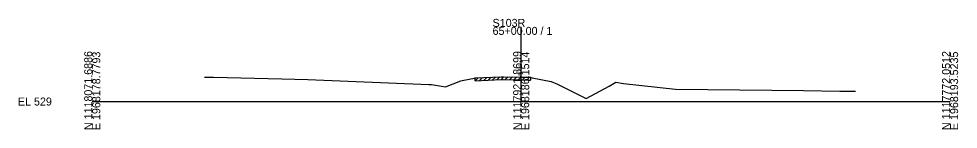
# Model space of a CAD drawing. Extents: x 974 to 1303, y 990 to 10019.
# Drawn here: x 974.3 to 1302.8, y 7490.3 to 7529 of the extents above; entities that cross this region are included whole.
import ezdxf

# ---------------------------------------------------------------- set-up
doc = ezdxf.new("R2010")
doc.units = 0
for name, color, linetype in [('Level 10', 7, 'Continuous'), ('Level 60', 7, 'Continuous'), ('Level 61', 7, 'Continuous'), ('Level 63', 7, 'Continuous')]:
    doc.layers.add(name, color=color, linetype=linetype)

msp = doc.modelspace()

# ---------------------------------------------------------------- linework, layer by layer
at = {"layer": 'Level 60'}
for p, q in [((1039.27, 7508.49), (1042.35, 7508.48)), ((1042.35, 7508.48), (1066.28, 7507.97)), ((1066.28, 7507.97), (1075.36, 7507.77)), ((1075.36, 7507.77), (1117.73, 7506.02)), ((1123.53, 7505.17), (1128.91, 7507.24)), ((1128.91, 7507.24), (1129.32, 7507.39)), ((1129.32, 7507.39), (1133.64, 7508.23)), ((1133.64, 7508.23), (1133.96, 7508.28)), ((1133.96, 7508.28), (1143.06, 7508.68)), ((1143.06, 7508.68), (1143.75, 7508.71)), ((1143.75, 7508.71), (1150, 7508.56)), ((1150, 7508.56), (1152.42, 7508.5)), ((1152.42, 7508.5), (1153.21, 7508.48)), ((1153.21, 7508.48), (1153.89, 7508.33)), ((1153.89, 7508.33), (1160.51, 7507.05)), ((1160.51, 7507.05), (1162.7, 7506.06)), ((1117.73, 7506.02), (1118.67, 7505.99)), ((1118.67, 7505.99), (1123.53, 7505.17)), ((1162.7, 7506.06), (1172.69, 7501.12)), ((1172.69, 7501.12), (1180.73, 7505.43)), ((1180.73, 7505.43), (1183.12, 7506.77)), ((1183.12, 7506.77), (1185.79, 7506.31)), ((1185.79, 7506.31), (1203.95, 7504.3)), ((1203.95, 7504.3), (1248.68, 7503.86)), ((1248.68, 7503.86), (1261.49, 7503.61)), ((1261.49, 7503.61), (1266.88, 7503.62))]:
    msp.add_line(p, q, dxfattribs=at)
at = {"layer": 'Level 61'}
for p, q in [((1133.96, 7507.28), (1135.01, 7508.33)), ((1133.96, 7507.28), (1133.96, 7508.28)), ((1133.96, 7507.28), (1143.06, 7507.68)), ((1135.46, 7507.35), (1136.51, 7508.4)), ((1136.96, 7507.42), (1138.01, 7508.46)), ((1138.46, 7507.48), (1139.51, 7508.53)), ((1139.96, 7507.55), (1141.01, 7508.59)), ((1141.46, 7507.61), (1142.51, 7508.66)), ((1142.96, 7507.68), (1143.99, 7508.71)), ((1143.06, 7507.68), (1143.75, 7507.71)), ((1143.75, 7507.71), (1150, 7507.56)), ((1144.46, 7507.7), (1145.44, 7508.67)), ((1145.96, 7507.66), (1146.94, 7508.64)), ((1147.46, 7507.62), (1148.44, 7508.6)), ((1148.96, 7507.59), (1149.94, 7508.56)), ((1150, 7507.56), (1152.42, 7507.5)), ((1150.46, 7507.55), (1151.44, 7508.53)), ((1151.96, 7507.52), (1152.93, 7508.49)), ((1152.42, 7507.5), (1153.21, 7507.48)), ((1153.21, 7508.48), (1153.21, 7507.48)), ((1153.21, 7507.48), (1153.21, 7507.48))]:
    msp.add_line(p, q, dxfattribs=at)
at = {"layer": 'Level 63'}
for p, q in [((1150, 7500), (1150, 7526.14)), ((1000, 7500), (1150, 7500)), ((1150, 7500), (1300, 7500))]:
    msp.add_line(p, q, dxfattribs=at)

# ---------------------------------------------------------------- texts
at = {"layer": 'Level 10'}
msp.add_text('537.56', height=0.9, rotation=90, dxfattribs=at).set_placement((1149.95, 7509.06))
at = {"layer": 'Level 63'}
for s, p in [('S103R', (1140, 7526.14)), ('65+00.00 / 1', (1140, 7523.34)), ('EL 529', (974, 7498.6))]:
    msp.add_text(s, height=2.8, dxfattribs=at).set_placement(p)
for s, p in [('N 1118071.6886', (1000, 7490)), ('E 1968178.7793', (1002.8, 7490)), ('N 1117921.8699', (1150, 7490)), ('E 1968186.1514', (1152.8, 7490)), ('N 1117772.0512', (1300, 7490)), ('E 1968193.5235', (1302.8, 7490))]:
    msp.add_text(s, height=2.8, rotation=90, dxfattribs=at).set_placement(p)

doc.saveas('drawing.dxf')
